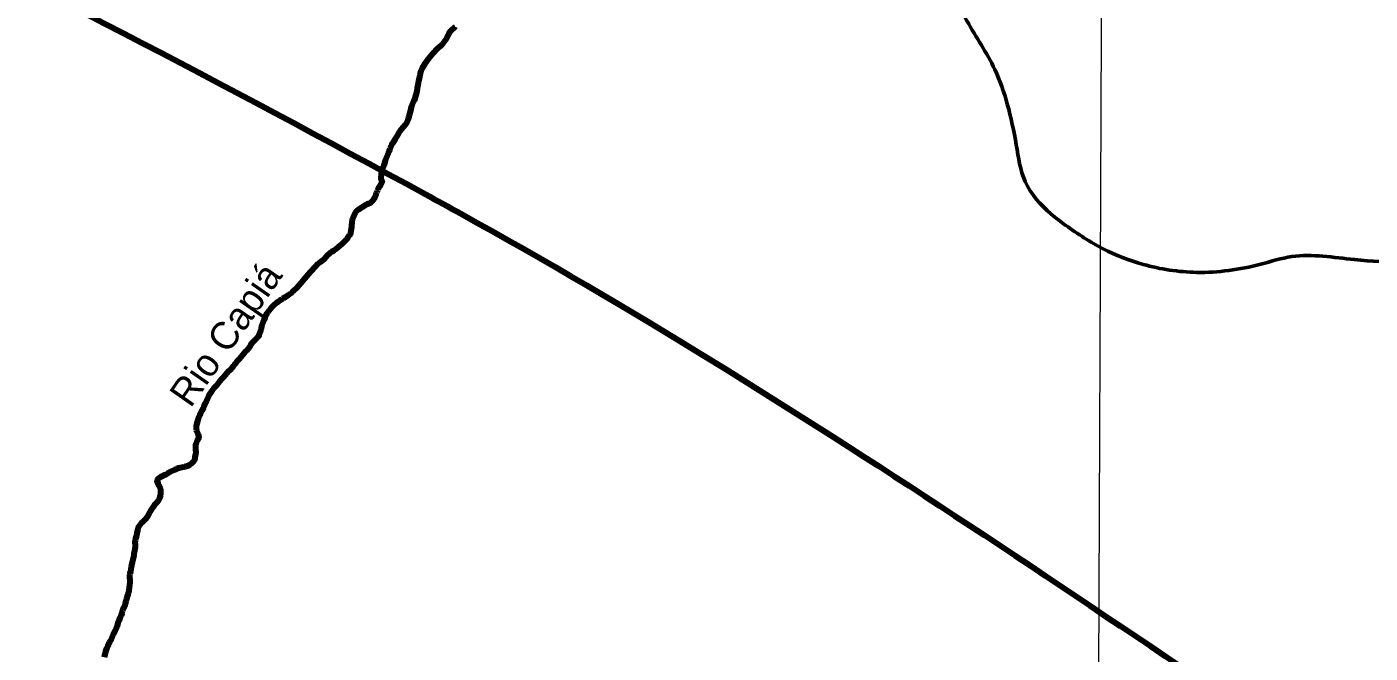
# Model space of a CAD drawing. Extents: x -1643653 to 4543381, y 1624270 to 13878484.
# Drawn here: x 645322 to 669599, y 8957118 to 8968437 of the extents above; entities that cross this region are included whole.
import ezdxf
from ezdxf.enums import TextEntityAlignment as Align

# ---------------------------------------------------------------- set-up
doc = ezdxf.new("R2010")
doc.units = 0
doc.header["$LTSCALE"] = 200
for name, color, linetype, lineweight in [('1', 7, 'Continuous', 13), ('24', 7, 'Continuous', 25), ('27', 7, 'Continuous', 13), ('28', 7, 'Continuous', 53), ('60', 7, 'Continuous', 13), ('9', 7, 'Continuous', 90)]:
    doc.layers.add(name, color=color, linetype=linetype, lineweight=lineweight)
doc.layers.add('49', color=7, linetype='Continuous')

msp = doc.modelspace()

# ---------------------------------------------------------------- linework, layer by layer
at = {"layer": '1'}
msp.add_lwpolyline([(664968.2, 9023436.8), (664657.1, 8949509), (664397.1, 8890880.2)], dxfattribs=at)
at = {"layer": '24', "lineweight": 53}
for points in [[(653061.9, 8968437.6), (653060, 8968431.6), (653055, 8968429.5), (653045.5, 8968418.5), (652999.2, 8968380.5), (652979.1, 8968362.1), (652966, 8968345), (652949.9, 8968318.3), (652925.3, 8968271.2), (652905.8, 8968224.1), (652891.4, 8968201.3), (652870.7, 8968180.1), (652835.3, 8968129.2), (652814.8, 8968105.2), (652767.5, 8968061.3), (652745.1, 8968043.8), (652652.7, 8967947.3), (652575.9, 8967853), (652512.8, 8967770.6), (652464.1, 8967693.3), (652444.9, 8967645.2), (652429.5, 8967596.4), (652427.1, 8967572.9), (652423, 8967550.1), (652401.8, 8967461), (652386.5, 8967384.3), (652386.5, 8967384.3), (652384.2, 8967360.8), (652378.1, 8967337.2), (652377.6, 8967311.9), (652365.4, 8967244.7), (652334.5, 8967142.4), (652334.2, 8967141.5)], [(652334.2, 8967141.5), (652324.2, 8967104.9), (652322.5, 8967102.9), (652317.1, 8967102.6), (652315.6, 8967101.2), (652313.2, 8967092.4), (652305.8, 8967079.3), (652284.1, 8967031.6), (652276.2, 8967009.5), (652248.5, 8966903.2), (652229.6, 8966839.8), (652226.8, 8966816.7), (652221.7, 8966796.1), (652207.8, 8966753.2), (652174.8, 8966688.9), (652160.4, 8966666.8), (652125.1, 8966623.9), (652084.5, 8966580), (652063.4, 8966553.7), (652047.7, 8966528.9), (652014.7, 8966461.6), (651981.7, 8966407.3), (651960.2, 8966375.4), (651944.1, 8966347.6), (651912.1, 8966302.5), (651898.2, 8966276.2), (651897.4, 8966264.9), (651885.1, 8966236.2), (651874.7, 8966216.8), (651867.7, 8966193.9), (651851, 8966156.5), (651798.1, 8966019.3), (651792.6, 8965994.6), (651772.9, 8965932.8), (651759.8, 8965907.9), (651741.4, 8965863.8), (651729.4, 8965826.5), (651723.3, 8965779.3), (651720.3, 8965699.1), (651722.8, 8965675), (651743.5, 8965648.6), (651743.4, 8965644.6), (651698.9, 8965564), (651693.6, 8965544.1), (651688.2, 8965540.4), (651686.5, 8965534.9), (651674.3, 8965514.2), (651664.3, 8965494.4), (651655.9, 8965471.5), (651645.4, 8965450), (651637.1, 8965429.3), (651623.4, 8965385), (651601.4, 8965342.9), (651591.7, 8965321.5), (651577.2, 8965299.5), (651559.6, 8965280.8), (651533.4, 8965257.4), (651515.3, 8965247.1), (651499.6, 8965244.2), (651496.3, 8965241.1), (651479.6, 8965235.3), (651466.6, 8965226.9), (651443.2, 8965217.1), (651307.6, 8965130.1), (651287.6, 8965112.6), (651272.7, 8965096.7), (651258.7, 8965075.1), (651231.1, 8965023.9), (651213.3, 8964982.5), (651203.9, 8964956.5), (651195.2, 8964907.3), (651191.2, 8964841.6), (651191, 8964817.2), (651164.9, 8964678.6), (651157.3, 8964676.2), (651155.4, 8964668.4), (651148.9, 8964664.2), (651138.2, 8964651.3), (651124.9, 8964632.4), (651105.4, 8964599.6), (651094.6, 8964583.9), (651089.5, 8964580.2), (651065.3, 8964555.2), (651012.9, 8964509), (650998.5, 8964498.8), (650986.4, 8964486.1), (650949.3, 8964456), (650900.6, 8964412.3), (650874.5, 8964393.6), (650844.8, 8964377.2), (650826.4, 8964368.8), (650809.3, 8964357.4), (650785.7, 8964337.7), (650747.8, 8964302.8), (650693.7, 8964240.3), (650662, 8964208.7), (650662, 8964208.7), (650632.1, 8964188.2), (650618, 8964175.7), (650604.2, 8964169.9), (650589.6, 8964160.3)], [(650589.6, 8964160.3), (650574.3, 8964146.5), (650530.2, 8964098.3), (650509, 8964077.9), (650473.5, 8964033), (650442.6, 8964005.1), (650368.1, 8963919.8), (650346, 8963888.5), (650332.8, 8963874.9), (650310.5, 8963845.9), (650278.5, 8963808.1), (650264.2, 8963793.4), (650207.7, 8963725.5), (650176.4, 8963697.3), (650153.9, 8963678.9), (650140.4, 8963665.7), (650124.7, 8963653.2), (650103.3, 8963631.9), (650086.5, 8963618), (650072.4, 8963608.2), (650060.6, 8963597.7), (650046.6, 8963590.1), (650000.4, 8963555.6), (649955.2, 8963530.6), (649939, 8963520), (649922.4, 8963511.9), (649893.1, 8963492), (649865.1, 8963469.6), (649835.2, 8963451.3), (649777.6, 8963401.4), (649742.6, 8963367.3), (649718.9, 8963335.7), (649704, 8963312.6), (649674.6, 8963276.8), (649661.2, 8963257.8), (649648.9, 8963237.2), (649640.8, 8963219.3), (649630.7, 8963202.8), (649615, 8963169.3), (649608.8, 8963150.8), (649584.8, 8963092.3), (649563.2, 8963031.5), (649555.5, 8962980.1), (649545.2, 8962946.6), (649541.4, 8962928), (649515.6, 8962859.5), (649507.1, 8962843.2), (649499.9, 8962833.4), (649481.2, 8962814.6), (649475.3, 8962806.6), (649456.2, 8962788.3), (649449.4, 8962778.8), (649420.2, 8962753.5), (649395, 8962724.1), (649367.2, 8962685.5), (649343.5, 8962648.1), (649319.4, 8962615.6), (649289.5, 8962584.5), (649264.9, 8962562.7), (649217.7, 8962504.2), (649187.2, 8962469.5), (649162, 8962433.2), (649131.5, 8962399.3), (649105.7, 8962365.4), (649075.9, 8962335.3), (649056.5, 8962311.9), (649027.9, 8962268.9), (649013.5, 8962252.7), (648961.3, 8962205.6), (648876.1, 8962105.7), (648858.3, 8962087.9), (648839.2, 8962071.7), (648801.6, 8962026.5), (648742.1, 8961950.5), (648715.9, 8961919), (648698.4, 8961903), (648678.4, 8961875.1), (648665.1, 8961852.7), (648623.9, 8961794), (648612.1, 8961775.1), (648600.3, 8961752.7), (648585.9, 8961717.7), (648566.1, 8961679.4), (648547.4, 8961632), (648528.6, 8961598.4), (648520.4, 8961575.2), (648506.1, 8961547), (648501.5, 8961529.9), (648482.2, 8961497.1), (648474.8, 8961478.5), (648456.4, 8961445.7), (648449.2, 8961427.1), (648419.2, 8961360.9), (648410.6, 8961337.9), (648398, 8961290.7), (648391.5, 8961272.8), (648380.9, 8961222.2), (648380.9, 8961222.2), (648379.8, 8961206.8), (648384.7, 8961171.6), (648385.1, 8961152.9)], [(648385.1, 8961152.9), (648390, 8961133.3), (648400.4, 8961103), (648415.7, 8961067.9), (648425.4, 8961050), (648432.1, 8961011), (648401.9, 8960963.6), (648376.2, 8960898.2), (648370.1, 8960878.6), (648367.8, 8960859.9), (648367.9, 8960810.1), (648376.5, 8960734.5), (648357.4, 8960665.8), (648358.8, 8960619.8), (648351.9, 8960604.5), (648338.8, 8960585.2), (648311.2, 8960556.4), (648291.8, 8960541.2), (648269.8, 8960521), (648236.7, 8960501.1), (648220, 8960496.4), (648202.2, 8960494.8), (648170.1, 8960481.9), (648153, 8960477.4), (648100.1, 8960468.4), (648066.6, 8960460), (648032.2, 8960447.3), (648014.3, 8960438.5), (647997.2, 8960433), (647928.7, 8960400.9), (647863.5, 8960365.3), (647826.2, 8960342.8), (647793.8, 8960329), (647778, 8960318.3), (647744.3, 8960305.3), (647701.1, 8960277.2), (647689.4, 8960265.4), (647679.9, 8960250.9), (647675, 8960238.2), (647674.2, 8960228.6), (647680.1, 8960220.4), (647683.5, 8960203.8), (647689.9, 8960186.8), (647698.1, 8960170.3), (647708.3, 8960153.8), (647730.9, 8960100.4), (647739.1, 8960063.9), (647740.2, 8960032), (647736.1, 8959980.6), (647731.8, 8959962.6), (647725, 8959943.9), (647716.7, 8959911.2), (647708.7, 8959892.6), (647696.4, 8959871.2), (647672.6, 8959842), (647653.3, 8959825.7), (647636.4, 8959806.1), (647604.7, 8959757.9), (647594, 8959736.3), (647570, 8959703.3), (647547.8, 8959670.1), (647506.1, 8959591.7), (647464.3, 8959538.3), (647419.4, 8959492.2), (647388.5, 8959466.3), (647353, 8959421.6), (647336.2, 8959394.4), (647325.8, 8959358.5), (647311.8, 8959293.5), (647311.1, 8959273.8), (647298.8, 8959224.9), (647287.2, 8959190.6), (647279.5, 8959155.6), (647275.4, 8959122.1), (647277.5, 8959069.1), (647277.3, 8959036.4), (647271.1, 8959002.1), (647267.7, 8958967.1), (647258.4, 8958917.2), (647255, 8958883), (647222.6, 8958760.6), (647213.1, 8958710), (647209.8, 8958675.8), (647197.2, 8958591.6), (647186.1, 8958559), (647181, 8958538.7), (647179, 8958522.3), (647180.3, 8958485.5), (647185.2, 8958453), (647182.2, 8958403.1), (647164.1, 8958249.7), (647150.1, 8958180.3), (647142.6, 8958162.4), (647125.2, 8958100), (647110, 8958058), (647106, 8958041.7), (647101.7, 8958008.2), (647087.2, 8957958.4), (647087.2, 8957958.4), (647058.3, 8957911.3), (647050.3, 8957890.4)], [(647050.3, 8957890.4), (647042.3, 8957873.9), (647037.4, 8957839), (647027, 8957805.4), (647004.7, 8957754), (646983.9, 8957699.7), (646975.5, 8957682.5), (646947.2, 8957596.2), (646930.5, 8957560.2), (646917.2, 8957527.6), (646883.4, 8957459.8), (646834.7, 8957341.3), (646821.9, 8957322.3), (646811.7, 8957303.4), (646805, 8957286.3), (646794.6, 8957269.1), (646788.3, 8957250.5), (646761.3, 8957200.6), (646741.4, 8957150.7), (646718.5, 8957047.1)]]:
    msp.add_lwpolyline(points, dxfattribs=at)
at = {"layer": '24'}
msp.add_spline([(665209.5, 8949437.1), (665261.8, 8949907.3), (665888.8, 8950560.5), (666750.9, 8951187.5), (667665.3, 8951814.5), (668344.5, 8952363.1), (668788.7, 8952911.7), (669180.6, 8953564.9), (669154.4, 8954270.2), (669755.3, 8954662.1), (670486.8, 8955027.9), (671218.3, 8955785.5), (671166.1, 8956360.3), (671531.8, 8956726), (671479.6, 8956987.3), (670957.1, 8957405.3), (670695.8, 8957849.4), (671139.9, 8958502.5), (671845.3, 8959207.9), (672394, 8958789.9), (673047.1, 8959234), (673465.1, 8959834.9), (673177.7, 8960461.9), (673987.6, 8960749.3), (675163.2, 8960879.9), (676103.7, 8960906.1), (677253.2, 8961428.6), (677697.4, 8961559.2), (678115.4, 8962133.9), (678611.8, 8962369.1), (678820.8, 8962919.9), (679291, 8963704.1), (679918, 8964226.8), (679944.1, 8964697.3), (679709, 8965272.3), (679291, 8966004.2), (678115.4, 8966945.2)], degree=3, dxfattribs=at)
at = {"layer": '27'}
msp.add_spline([(655983.7, 8975399.4), (656923, 8974848.7), (657608.5, 8974464.4), (658343, 8973736.5), (658963.6, 8973136.3), (659596.6, 8972485.1), (660330.5, 8971655.5), (660495.7, 8971591.2), (661115.6, 8970863.8), (661404.1, 8970086.9), (661693.8, 8969526.2), (662110.5, 8968901.3), (662312.2, 8968544.4), (662816.6, 8967664.9), (663042.2, 8967040.8), (663203.6, 8966302.6), (663365.3, 8965640.7), (663833.2, 8965053.8), (664099.5, 8964849.2), (664772, 8964426.8), (665496.3, 8964144), (666463.4, 8964000.2), (667623.1, 8964148), (668184.3, 8964285.6), (669317.4, 8964230), (670221.1, 8964150), (671187.7, 8963917.1), (671823.3, 8963711.1), (672497.1, 8963517.5), (673386.9, 8963221.4), (674492.1, 8962733.6), (675125.5, 8962146), (675556, 8961711.9), (676150.3, 8960959.1), (676174.9, 8960921)], degree=3, dxfattribs=at)
at = {"layer": '28'}
for points in [[(676174.9, 8960921), (676150.3, 8960959.1), (675556, 8961711.9), (675125.5, 8962146), (674492.1, 8962733.6), (673386.9, 8963221.4), (672497.1, 8963517.5), (671823.3, 8963711.1), (671187.7, 8963917.1), (670221.1, 8964150), (669317.4, 8964230), (668184.3, 8964285.6), (667623.1, 8964148), (666463.4, 8964000.2), (665496.3, 8964144), (664772, 8964426.8), (664099.5, 8964849.2), (663833.2, 8965053.8), (663365.3, 8965640.7), (663203.6, 8966302.6), (663042.2, 8967040.8), (662816.6, 8967664.9), (662312.2, 8968544.4), (662110.5, 8968901.3), (661693.8, 8969526.2), (661404.1, 8970086.9), (661115.6, 8970863.8), (660495.7, 8971591.2), (660330.5, 8971655.5), (659596.6, 8972485.1), (658963.6, 8973136.3), (658343, 8973736.5), (657608.5, 8974464.4), (656923, 8974848.7), (655983.7, 8975399.4)], [(665209.5, 8949437.1), (665261.8, 8949907.3), (665888.8, 8950560.5), (666750.9, 8951187.5), (667665.3, 8951814.5), (668344.5, 8952363.1), (668788.7, 8952911.7), (669180.6, 8953564.9), (669154.4, 8954270.2), (669755.3, 8954662.1), (670486.8, 8955027.9), (671218.3, 8955785.5), (671166.1, 8956360.3), (671531.8, 8956726), (671479.6, 8956987.3), (670957.1, 8957405.3), (670695.8, 8957849.4), (671139.9, 8958502.5), (671845.3, 8959207.9), (672394, 8958789.9), (673047.1, 8959234), (673465.1, 8959834.9), (673177.7, 8960461.9), (673987.6, 8960749.3), (675163.2, 8960879.9), (676103.7, 8960906.1), (676174.9, 8960921)], [(676174.9, 8960894.8), (676103.7, 8960879.9), (675163.2, 8960853.8), (673987.6, 8960723.2), (673177.7, 8960435.8), (673465.1, 8959808.8), (673047.1, 8959207.9), (672394, 8958763.8), (671845.3, 8959181.8), (671139.9, 8958476.4), (670695.8, 8957823.2), (670957.1, 8957379.1), (671479.6, 8956961.1), (671531.8, 8956699.9), (671166.1, 8956334.1), (671218.3, 8955759.3), (670486.8, 8955001.7), (669755.3, 8954636), (669154.4, 8954244.1), (669180.6, 8953538.7), (668788.7, 8952885.6), (668344.5, 8952337), (667665.3, 8951788.3), (666750.9, 8951161.3), (665888.8, 8950534.3), (665261.8, 8949881.2), (665209.5, 8949410.9)]]:
    msp.add_spline(points, degree=3, dxfattribs=at)
at = {"layer": '60', "lineweight": 25}
msp.add_spline([(814781, 9009175.5), (814787.2, 9009173.4), (814796.9, 9009173.4), (814799.4, 9009172.4), (814805.1, 9009174.5), (814805.6, 9009176.5), (814811.7, 9009179.5), (814811.7, 9009179.5), (814801.5, 9009181), (814790.7, 9009181.5), (814784.1, 9009183.1), (814777.4, 9009185.1), (814778.4, 9009175.5)], degree=3, dxfattribs=at)
at = {"layer": '9'}
for points in [[(653061.9, 8968437.6), (653060, 8968431.6), (653055, 8968429.5), (653045.5, 8968418.5), (652999.2, 8968380.5), (652979.1, 8968362.1), (652966, 8968345), (652949.9, 8968318.3), (652925.3, 8968271.2), (652905.8, 8968224.1), (652891.4, 8968201.3), (652870.7, 8968180.1), (652835.3, 8968129.2), (652814.8, 8968105.2), (652767.5, 8968061.3), (652745.1, 8968043.8), (652652.7, 8967947.3), (652575.9, 8967853), (652512.8, 8967770.6), (652464.1, 8967693.3), (652444.9, 8967645.2), (652429.5, 8967596.4), (652427.1, 8967572.9), (652423, 8967550.1), (652401.8, 8967461), (652386.5, 8967384.3), (652386.5, 8967384.3), (652384.2, 8967360.8), (652378.1, 8967337.2), (652377.6, 8967311.9), (652365.4, 8967244.7), (652334.5, 8967142.4), (652334.2, 8967141.5)], [(652334.2, 8967141.5), (652324.2, 8967104.9), (652322.5, 8967102.9), (652317.1, 8967102.6), (652315.6, 8967101.2), (652313.2, 8967092.4), (652305.8, 8967079.3), (652284.1, 8967031.6), (652276.2, 8967009.5), (652248.5, 8966903.2), (652229.6, 8966839.8), (652226.8, 8966816.7), (652221.7, 8966796.1), (652207.8, 8966753.2), (652174.8, 8966688.9), (652160.4, 8966666.8), (652125.1, 8966623.9), (652084.5, 8966580), (652063.4, 8966553.7), (652047.7, 8966528.9), (652014.7, 8966461.6), (651981.7, 8966407.3), (651960.2, 8966375.4), (651944.1, 8966347.6), (651912.1, 8966302.5), (651898.2, 8966276.2), (651897.4, 8966264.9), (651885.1, 8966236.2), (651874.7, 8966216.8), (651867.7, 8966193.9), (651851, 8966156.5), (651798.1, 8966019.3), (651792.6, 8965994.6), (651772.9, 8965932.8), (651759.8, 8965907.9), (651741.4, 8965863.8), (651729.4, 8965826.5), (651723.3, 8965779.3), (651720.3, 8965699.1), (651722.8, 8965675), (651743.5, 8965648.6), (651743.4, 8965644.6), (651698.9, 8965564), (651693.6, 8965544.1), (651688.2, 8965540.4), (651686.5, 8965534.9), (651674.3, 8965514.2), (651664.3, 8965494.4), (651655.9, 8965471.5), (651645.4, 8965450), (651637.1, 8965429.3), (651623.4, 8965385), (651601.4, 8965342.9), (651591.7, 8965321.5), (651577.2, 8965299.5), (651559.6, 8965280.8), (651533.4, 8965257.4), (651515.3, 8965247.1), (651499.6, 8965244.2), (651496.3, 8965241.1), (651479.6, 8965235.3), (651466.6, 8965226.9), (651443.2, 8965217.1), (651307.6, 8965130.1), (651287.6, 8965112.6), (651272.7, 8965096.7), (651258.7, 8965075.1), (651231.1, 8965023.9), (651213.3, 8964982.5), (651203.9, 8964956.5), (651195.2, 8964907.3), (651191.2, 8964841.6), (651191, 8964817.2), (651164.9, 8964678.6), (651157.3, 8964676.2), (651155.4, 8964668.4), (651148.9, 8964664.2), (651138.2, 8964651.3), (651124.9, 8964632.4), (651105.4, 8964599.6), (651094.6, 8964583.9), (651089.5, 8964580.2), (651065.3, 8964555.2), (651012.9, 8964509), (650998.5, 8964498.8), (650986.4, 8964486.1), (650949.3, 8964456), (650900.6, 8964412.3), (650874.5, 8964393.6), (650844.8, 8964377.2), (650826.4, 8964368.8), (650809.3, 8964357.4), (650785.7, 8964337.7), (650747.8, 8964302.8), (650693.7, 8964240.3), (650662, 8964208.7), (650662, 8964208.7), (650632.1, 8964188.2), (650618, 8964175.7), (650604.2, 8964169.9), (650589.6, 8964160.3)], [(650589.6, 8964160.3), (650574.3, 8964146.5), (650530.2, 8964098.3), (650509, 8964077.9), (650473.5, 8964033), (650442.6, 8964005.1), (650368.1, 8963919.8), (650346, 8963888.5), (650332.8, 8963874.9), (650310.5, 8963845.9), (650278.5, 8963808.1), (650264.2, 8963793.4), (650207.7, 8963725.5), (650176.4, 8963697.3), (650153.9, 8963678.9), (650140.4, 8963665.7), (650124.7, 8963653.2), (650103.3, 8963631.9), (650086.5, 8963618), (650072.4, 8963608.2), (650060.6, 8963597.7), (650046.6, 8963590.1), (650000.4, 8963555.6), (649955.2, 8963530.6), (649939, 8963520), (649922.4, 8963511.9), (649893.1, 8963492), (649865.1, 8963469.6), (649835.2, 8963451.3), (649777.6, 8963401.4), (649742.6, 8963367.3), (649718.9, 8963335.7), (649704, 8963312.6), (649674.6, 8963276.8), (649661.2, 8963257.8), (649648.9, 8963237.2), (649640.8, 8963219.3), (649630.7, 8963202.8), (649615, 8963169.3), (649608.8, 8963150.8), (649584.8, 8963092.3), (649563.2, 8963031.5), (649555.5, 8962980.1), (649545.2, 8962946.6), (649541.4, 8962928), (649515.6, 8962859.5), (649507.1, 8962843.2), (649499.9, 8962833.4), (649481.2, 8962814.6), (649475.3, 8962806.6), (649456.2, 8962788.3), (649449.4, 8962778.8), (649420.2, 8962753.5), (649395, 8962724.1), (649367.2, 8962685.5), (649343.5, 8962648.1), (649319.4, 8962615.6), (649289.5, 8962584.5), (649264.9, 8962562.7), (649217.7, 8962504.2), (649187.2, 8962469.5), (649162, 8962433.2), (649131.5, 8962399.3), (649105.7, 8962365.4), (649075.9, 8962335.3), (649056.5, 8962311.9), (649027.9, 8962268.9), (649013.5, 8962252.7), (648961.3, 8962205.6), (648876.1, 8962105.7), (648858.3, 8962087.9), (648839.2, 8962071.7), (648801.6, 8962026.5), (648742.1, 8961950.5), (648715.9, 8961919), (648698.4, 8961903), (648678.4, 8961875.1), (648665.1, 8961852.7), (648623.9, 8961794), (648612.1, 8961775.1), (648600.3, 8961752.7), (648585.9, 8961717.7), (648566.1, 8961679.4), (648547.4, 8961632), (648528.6, 8961598.4), (648520.4, 8961575.2), (648506.1, 8961547), (648501.5, 8961529.9), (648482.2, 8961497.1), (648474.8, 8961478.5), (648456.4, 8961445.7), (648449.2, 8961427.1), (648419.2, 8961360.9), (648410.6, 8961337.9), (648398, 8961290.7), (648391.5, 8961272.8), (648380.9, 8961222.2), (648380.9, 8961222.2), (648379.8, 8961206.8), (648384.7, 8961171.6), (648385.1, 8961152.9)], [(648385.1, 8961152.9), (648390, 8961133.3), (648400.4, 8961103), (648415.7, 8961067.9), (648425.4, 8961050), (648432.1, 8961011), (648401.9, 8960963.6), (648376.2, 8960898.2), (648370.1, 8960878.6), (648367.8, 8960859.9), (648367.9, 8960810.1), (648376.5, 8960734.5), (648357.4, 8960665.8), (648358.8, 8960619.8), (648351.9, 8960604.5), (648338.8, 8960585.2), (648311.2, 8960556.4), (648291.8, 8960541.2), (648269.8, 8960521), (648236.7, 8960501.1), (648220, 8960496.4), (648202.2, 8960494.8), (648170.1, 8960481.9), (648153, 8960477.4), (648100.1, 8960468.4), (648066.6, 8960460), (648032.2, 8960447.3), (648014.3, 8960438.5), (647997.2, 8960433), (647928.7, 8960400.9), (647863.5, 8960365.3), (647826.2, 8960342.8), (647793.8, 8960329), (647778, 8960318.3), (647744.3, 8960305.3), (647701.1, 8960277.2), (647689.4, 8960265.4), (647679.9, 8960250.9), (647675, 8960238.2), (647674.2, 8960228.6), (647680.1, 8960220.4), (647683.5, 8960203.8), (647689.9, 8960186.8), (647698.1, 8960170.3), (647708.3, 8960153.8), (647730.9, 8960100.4), (647739.1, 8960063.9), (647740.2, 8960032), (647736.1, 8959980.6), (647731.8, 8959962.6), (647725, 8959943.9), (647716.7, 8959911.2), (647708.7, 8959892.6), (647696.4, 8959871.2), (647672.6, 8959842), (647653.3, 8959825.7), (647636.4, 8959806.1), (647604.7, 8959757.9), (647594, 8959736.3), (647570, 8959703.3), (647547.8, 8959670.1), (647506.1, 8959591.7), (647464.3, 8959538.3), (647419.4, 8959492.2), (647388.5, 8959466.3), (647353, 8959421.6), (647336.2, 8959394.4), (647325.8, 8959358.5), (647311.8, 8959293.5), (647311.1, 8959273.8), (647298.8, 8959224.9), (647287.2, 8959190.6), (647279.5, 8959155.6), (647275.4, 8959122.1), (647277.5, 8959069.1), (647277.3, 8959036.4), (647271.1, 8959002.1), (647267.7, 8958967.1), (647258.4, 8958917.2), (647255, 8958883), (647222.6, 8958760.6), (647213.1, 8958710), (647209.8, 8958675.8), (647197.2, 8958591.6), (647186.1, 8958559), (647181, 8958538.7), (647179, 8958522.3), (647180.3, 8958485.5), (647185.2, 8958453), (647182.2, 8958403.1), (647164.1, 8958249.7), (647150.1, 8958180.3), (647142.6, 8958162.4), (647125.2, 8958100), (647110, 8958058), (647106, 8958041.7), (647101.7, 8958008.2), (647087.2, 8957958.4), (647087.2, 8957958.4), (647058.3, 8957911.3), (647050.3, 8957890.4)], [(647050.3, 8957890.4), (647042.3, 8957873.9), (647037.4, 8957839), (647027, 8957805.4), (647004.7, 8957754), (646983.9, 8957699.7), (646975.5, 8957682.5), (646947.2, 8957596.2), (646930.5, 8957560.2), (646917.2, 8957527.6), (646883.4, 8957459.8), (646834.7, 8957341.3), (646821.9, 8957322.3), (646811.7, 8957303.4), (646805, 8957286.3), (646794.6, 8957269.1), (646788.3, 8957250.5), (646761.3, 8957200.6), (646741.4, 8957150.7), (646718.5, 8957047.1)]]:
    msp.add_lwpolyline(points, dxfattribs=at)
msp.add_spline([(637260.6, 8972975.8), (641524.5, 8971056.2), (652526.1, 8965412.7), (653164.3, 8965062.8), (670790.5, 8953770.1), (686194, 8943929.9), (696283.3, 8937647.1)], degree=3, dxfattribs=at)

# ---------------------------------------------------------------- texts
at = {"layer": '49'}
msp.add_text('Rio Capiá', height=500, rotation=55.114, dxfattribs=at).set_placement((649119.7, 8962738.4), align=Align.CENTER)

doc.saveas('drawing.dxf')
